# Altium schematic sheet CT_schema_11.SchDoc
size 391 x 238 mm
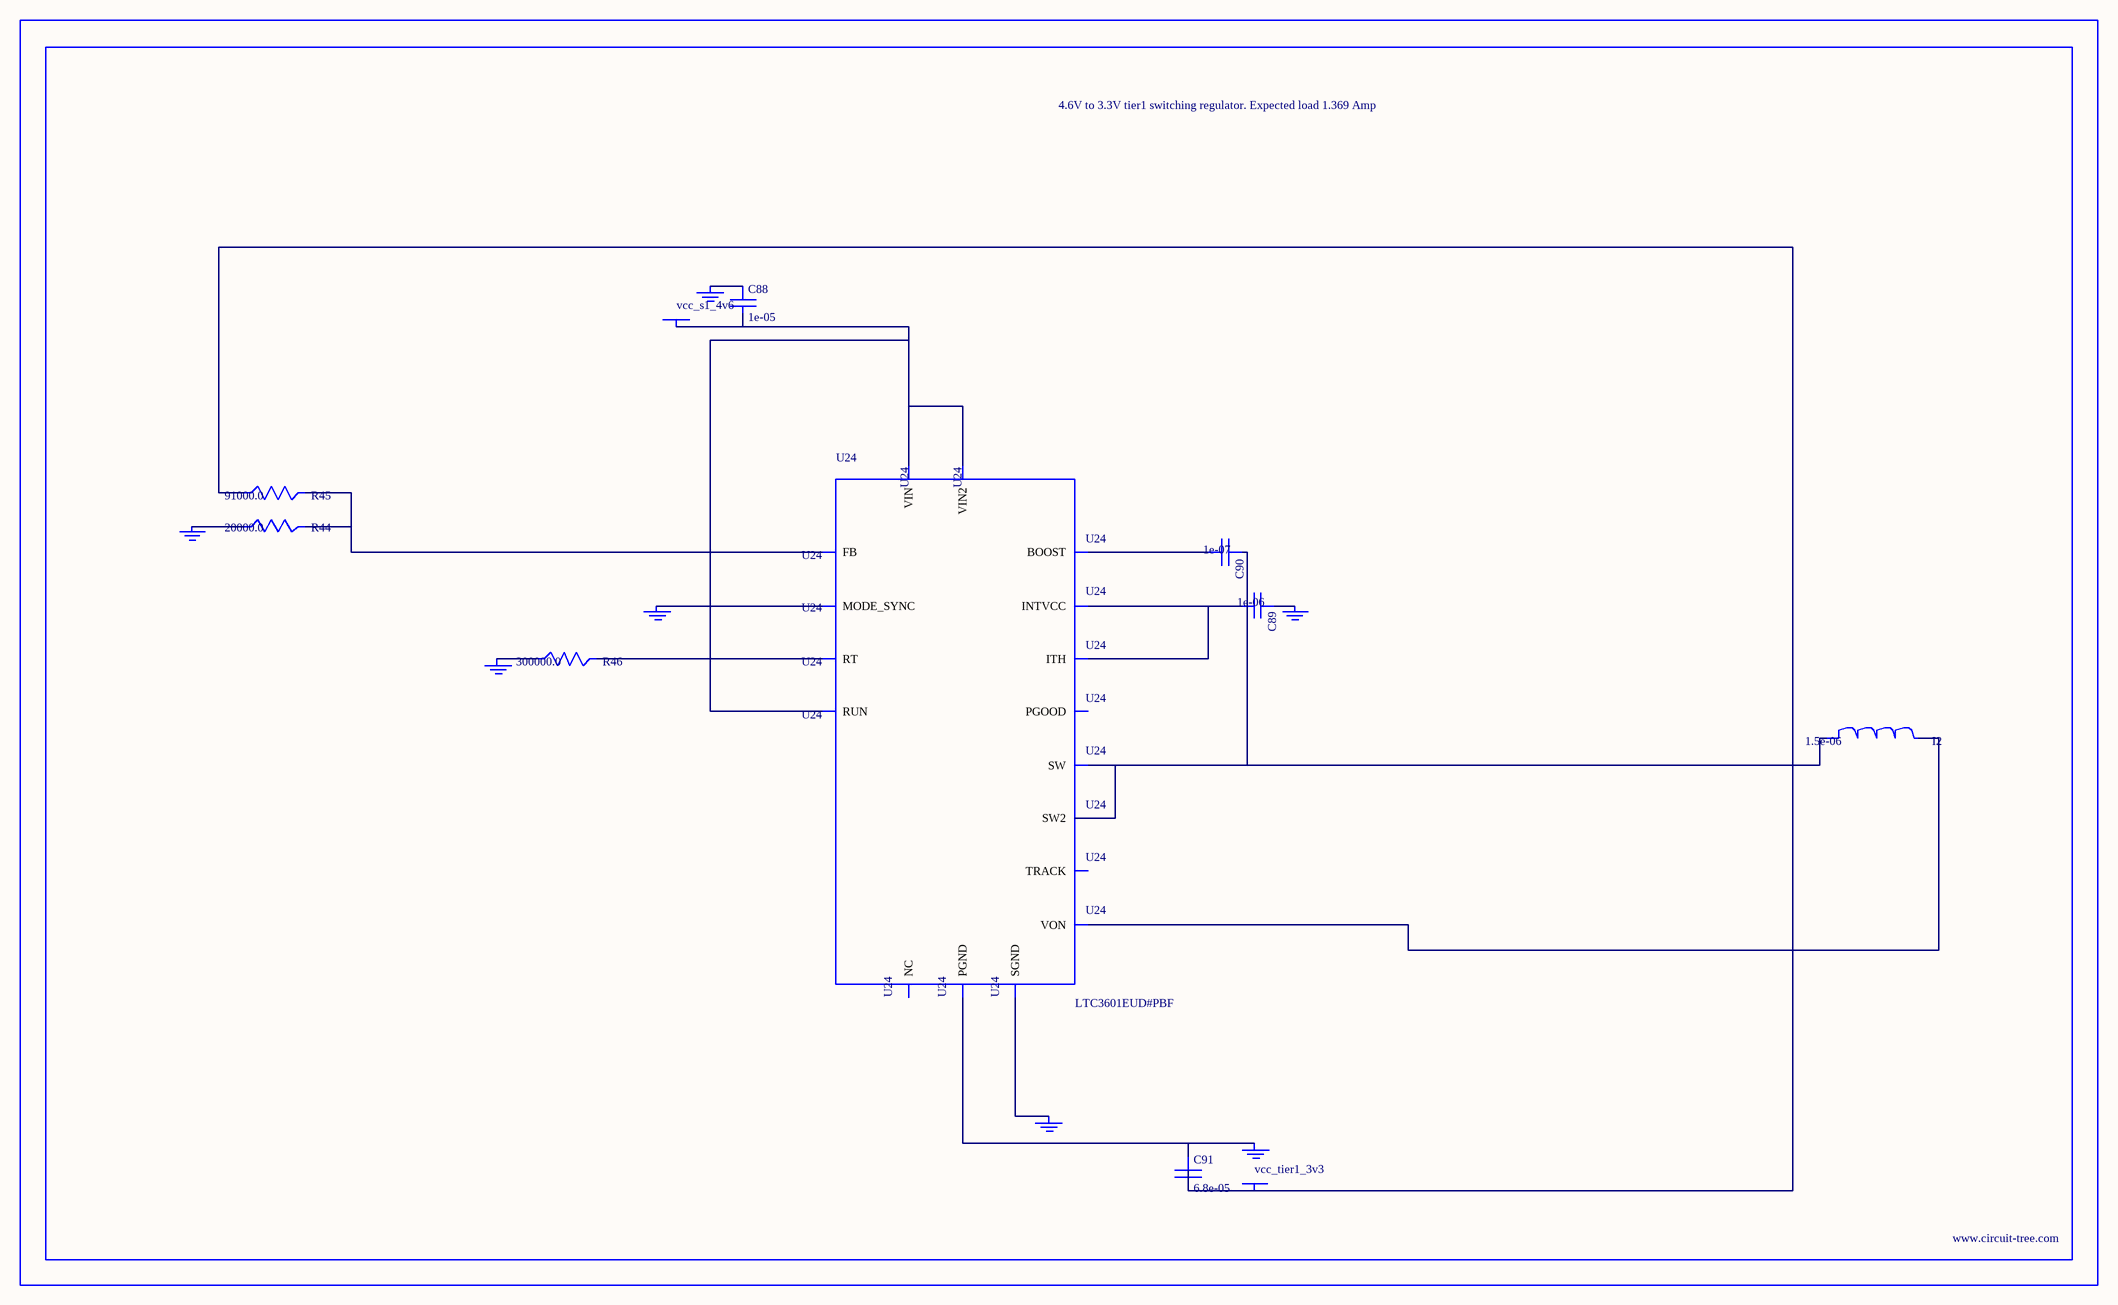
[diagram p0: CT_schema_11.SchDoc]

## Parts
BORDER10  (no value)
C88  1e-05  [C0805]
C89  1e-06  [C0603]
C90  1e-07  [C0402]
C91  6.8e-05  [2220]
GND_INSTANCE_10_0  (no value)
GND_INSTANCE_10_1  (no value)
GND_INSTANCE_10_2  (no value)
GND_INSTANCE_10_3  (no value)
GND_INSTANCE_10_4  (no value)
GND_INSTANCE_10_5  (no value)
GND_INSTANCE_10_6  (no value)
I2  1.5e-06  [IND_PM3316]
POWER_INSTANCE_10_0  vcc_s1_4v6
POWER_INSTANCE_10_1  vcc_tier1_3v3
R44  20000.0  [R0603]
R45  91000.0  [R0603]
R46  300000.0  [R0603]
U24  LTC3601EUD#PBF  [QFN-16_EP]

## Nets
NetC88_1: C88.1 GND_INSTANCE_10_5.0(GND)
NetC88_2: C88.2 POWER_INSTANCE_10_0.0(PWR) U24.14(RUN) U24.15(VIN) U24.16(VIN2)
NetC89_1: C89.1 GND_INSTANCE_10_1.0(GND)
NetC89_2: C89.2 U24.7(INTVCC) U24.12(ITH)
NetC90_1: C90.1 I2.1 U24.3(SW) U24.4(SW2)
NetC90_2: C90.2 U24.6(BOOST)
NetC91_1: C91.1 GND_INSTANCE_10_6.0(GND) U24.17(PGND)
NetC91_2: C91.2 I2.2 POWER_INSTANCE_10_1.0(PWR) R45.1 U24.8(VON)
NetGND_INSTANCE_10_0_0: GND_INSTANCE_10_0.0(GND) U24.1(MODE_SYNC)
NetGND_INSTANCE_10_2_0: GND_INSTANCE_10_2.0(GND) U24.9(SGND)
NetGND_INSTANCE_10_3_0: GND_INSTANCE_10_3.0(GND) R46.1
NetGND_INSTANCE_10_4_0: GND_INSTANCE_10_4.0(GND) R44.1
NetR44_2: R44.2 R45.2 U24.11(FB)
NetR46_2: R46.2 U24.10(RT)

Not connected (* = marked no-connect by the designer): U24 2(PGOOD) 5(NC) 13(TRACK)

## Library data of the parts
BORDER10 = BORDER_PAGE10
C88 = C0805C106K8RACTU
C89 = C0603C105K3RACTU
C90 = C0402C104K3RACTU
C91 = C5750X5R1A686M
GND_INSTANCE_10_0-GND_INSTANCE_10_6 = GND
I2 = PM3316-1R5M-RC
POWER_INSTANCE_10_0 POWER_INSTANCE_10_1 = PWR
R44 = RC0603JR-0720KL
R45 = RC0603JR-0791KL
R46 = RC0603JR-07300KL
